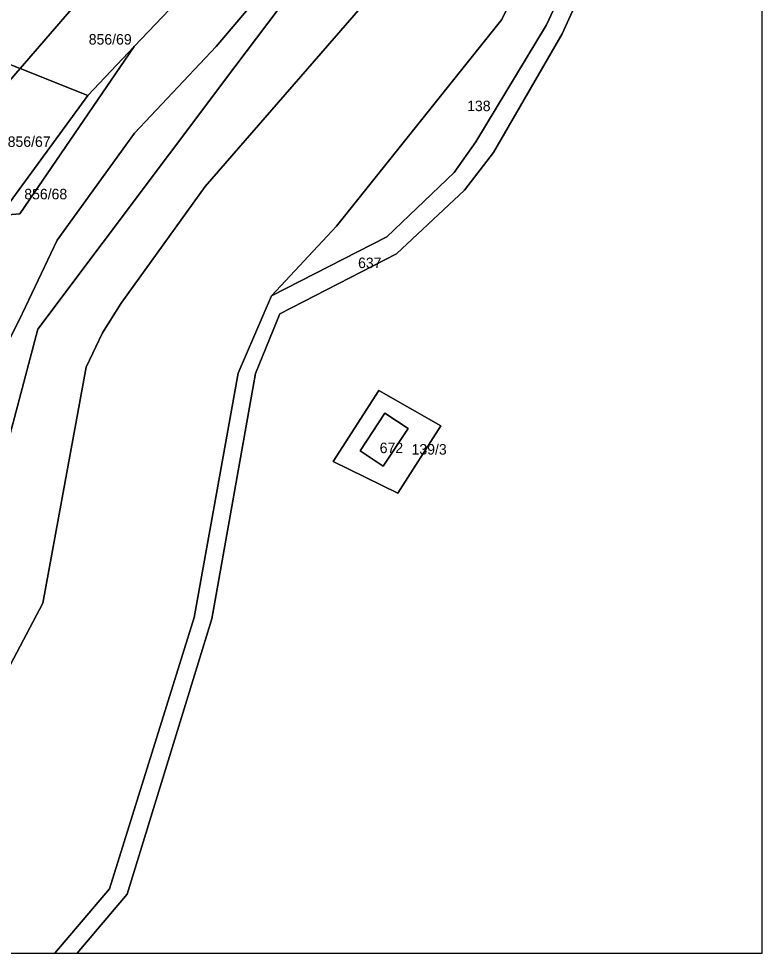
# Model space of a CAD drawing. Extents: x -564940 to -564406, y -1066466 to -1066072.
# Drawn here: x -564548.1 to -564406.4, y -1066465.6 to -1066287.6 of the extents above; entities that cross this region are included whole.
import ezdxf

# ---------------------------------------------------------------- set-up
doc = ezdxf.new("R2010")
doc.units = 0
doc.layers.add('ft_parcela_polygon', color=7, linetype='Continuous')
doc.layers.add('ft_parcela_text', color=7, linetype='Continuous')

msp = doc.modelspace()

# ---------------------------------------------------------------- linework, layer by layer
at = {"layer": 'ft_parcela_polygon'}
for p, q in [((-564582.26, -1066465.63), (-564541.21, -1066465.63)), ((-564541.21, -1066465.63), (-564536.97, -1066465.63))]:
    msp.add_line(p, q, dxfattribs=at)
for points in [[(-564506.93, -1066072.02), (-564500.76, -1066095.62), (-564490.54, -1066131.29), (-564485.08, -1066150.07), (-564474.86, -1066195.24), (-564468.44, -1066228.77), (-564474.86, -1066248.97), (-564479.58, -1066256.49), (-564510.51, -1066292.89), (-564526.05, -1066309.43), (-564540.77, -1066329.78), (-564548.05, -1066345), (-564588.23, -1066424.58), (-564607.75, -1066462.97), (-564609.27, -1066465.63)], [(-564609.27, -1066465.63), (-564607.75, -1066462.97), (-564588.23, -1066424.58), (-564548.05, -1066345), (-564540.77, -1066329.78), (-564526.05, -1066309.43), (-564510.51, -1066292.89), (-564479.58, -1066256.49), (-564474.86, -1066248.97), (-564468.44, -1066228.77), (-564474.86, -1066195.24), (-564485.08, -1066150.07), (-564490.54, -1066131.29), (-564500.76, -1066095.62), (-564506.93, -1066072.02)], [(-564600.77, -1066465.63), (-564576.34, -1066428.17), (-564561.1, -1066399.98), (-564552.57, -1066377.06), (-564544.46, -1066346.76), (-564506.9, -1066296.8), (-564477.41, -1066257.73), (-564467.26, -1066239.44), (-564459.83, -1066220.33), (-564457.63, -1066204.67), (-564458.61, -1066193.4), (-564464.89, -1066162.6), (-564473.06, -1066136.49), (-564496.21, -1066076.34), (-564497.57, -1066072.02)], [(-564497.57, -1066072.02), (-564496.21, -1066076.34), (-564473.06, -1066136.49), (-564464.89, -1066162.6), (-564458.61, -1066193.4), (-564457.63, -1066204.67), (-564459.83, -1066220.33), (-564467.26, -1066239.44), (-564477.41, -1066257.73), (-564506.9, -1066296.8), (-564544.46, -1066346.76), (-564552.57, -1066377.06), (-564561.1, -1066399.98), (-564576.34, -1066428.17), (-564600.77, -1066465.63)], [(-564428.01, -1066072.02), (-564431.34, -1066090.43), (-564438.01, -1066109.82), (-564446.27, -1066122.38), (-564434.59, -1066131.44), (-564440.14, -1066155.47), (-564448.27, -1066160.12), (-564443.92, -1066174.88), (-564442.56, -1066204.14), (-564447.75, -1066227.88), (-564462.14, -1066258.44), (-564480.38, -1066282.47), (-564512.56, -1066319.56), (-564528.58, -1066341.81), (-564532.13, -1066347.45), (-564535.25, -1066353.98), (-564543.55, -1066398.93), (-564558.38, -1066426.97), (-564582.26, -1066465.63)], [(-564582.26, -1066465.63), (-564558.38, -1066426.97), (-564543.55, -1066398.93), (-564535.25, -1066353.98), (-564532.13, -1066347.45), (-564528.58, -1066341.81), (-564512.56, -1066319.56), (-564480.38, -1066282.47), (-564462.14, -1066258.44), (-564447.75, -1066227.88), (-564442.56, -1066204.14), (-564443.92, -1066174.88), (-564448.27, -1066160.12), (-564456.43, -1066140.31), (-564460.8, -1066129.7), (-564472.45, -1066131.84), (-564488.63, -1066076.11), (-564489.48, -1066072.02)], [(-564541.21, -1066465.63), (-564530.8, -1066453.36), (-564514.67, -1066401.65), (-564506.28, -1066355.11), (-564499.92, -1066340.4), (-564487.53, -1066327.09), (-564456.06, -1066287.78), (-564438.54, -1066251.61), (-564424.63, -1066211.38), (-564406.38, -1066194.67)], [(-564406.38, -1066194.67), (-564424.63, -1066211.38), (-564434.8, -1066257.18), (-564442.13, -1066277.1), (-564447.53, -1066288.75), (-564461, -1066311.08), (-564465.11, -1066316.9), (-564477.95, -1066329.15), (-564499.92, -1066340.4), (-564506.28, -1066355.11), (-564514.67, -1066401.65), (-564530.8, -1066453.36), (-564541.21, -1066465.63)], [(-564536.97, -1066465.63), (-564406.38, -1066465.63), (-564406.38, -1066200.52)], [(-564406.38, -1066200.52), (-564421.59, -1066214.8), (-564431.36, -1066257.94), (-564438.67, -1066277.58), (-564444.56, -1066290.5), (-564457.61, -1066313.12), (-564463.15, -1066320.26), (-564476.08, -1066332.39), (-564498.32, -1066343.85), (-564502.98, -1066355.17), (-564511.33, -1066401.93), (-564527.46, -1066454.39), (-564536.97, -1066465.63)], [(-564536.97, -1066465.63), (-564527.46, -1066454.39), (-564511.33, -1066401.93), (-564502.98, -1066355.17), (-564498.32, -1066343.85), (-564476.08, -1066332.39), (-564463.15, -1066320.26), (-564457.61, -1066313.12), (-564444.56, -1066290.5), (-564438.67, -1066277.58), (-564431.36, -1066257.94), (-564421.59, -1066214.8), (-564406.38, -1066200.52)], [(-564519.39, -1066285.88), (-564526.09, -1066292.91), (-564547.92, -1066324.79), (-564551.67, -1066325.09), (-564555.65, -1066325.14), (-564559.33, -1066331.43), (-564556.55, -1066333.83), (-564553.56, -1066336.41), (-564579.89, -1066388.86), (-564586.69, -1066402.39), (-564589.7, -1066408.39), (-564595.81, -1066420.56), (-564609.5, -1066447.82), (-564620.81, -1066465.63)], [(-564467.66, -1066365.16), (-564475.84, -1066377.97), (-564488.17, -1066371.94), (-564479.46, -1066358.44), (-564467.66, -1066365.16)]]:
    msp.add_lwpolyline(points, dxfattribs=at)
for points in [[(-564499.92, -1066340.4), (-564477.95, -1066329.15), (-564465.11, -1066316.9), (-564461, -1066311.08), (-564447.53, -1066288.75), (-564442.13, -1066277.1), (-564434.8, -1066257.18), (-564424.63, -1066211.38), (-564438.54, -1066251.61), (-564456.06, -1066287.78), (-564487.53, -1066327.09)], [(-564532.7, -1066279.57), (-564567.5, -1066263.08), (-564578.22, -1066284.98), (-564558.28, -1066292.94), (-564547.86, -1066297.09)], [(-564534.97, -1066302.23), (-564526.09, -1066292.91), (-564519.39, -1066285.88), (-564532.7, -1066279.57), (-564547.86, -1066297.09)], [(-564547.86, -1066297.09), (-564558.28, -1066292.94), (-564559.2, -1066294.72), (-564561.47, -1066299.1), (-564565.88, -1066307.63), (-564568.76, -1066306.14), (-564574, -1066317.25), (-564567.34, -1066319.59)], [(-564551.67, -1066325.09), (-564547.92, -1066324.79), (-564526.09, -1066292.91), (-564534.97, -1066302.23)], [(-564567.34, -1066319.59), (-564551.67, -1066325.09), (-564534.97, -1066302.23), (-564547.86, -1066297.09)], [(-564488.17, -1066371.94), (-564475.84, -1066377.97), (-564467.66, -1066365.16), (-564479.46, -1066358.44)], [(-564473.88, -1066365.68), (-564478.3, -1066362.75), (-564483.04, -1066369.89), (-564478.62, -1066372.82)], [(-564483.04, -1066369.89), (-564478.3, -1066362.75), (-564473.88, -1066365.68), (-564478.62, -1066372.82)]]:
    msp.add_lwpolyline(points, close=True, dxfattribs=at)

# ---------------------------------------------------------------- texts
at = {"layer": 'ft_parcela_text'}
for s, p in [('856/69', (-564534.77, -1066292.53)), ('138', (-564462.64, -1066305.21)), ('856/67', (-564550.22, -1066312.02)), ('856/68', (-564547.06, -1066322.01)), ('637', (-564483.43, -1066335.11)), ('672', (-564479.31, -1066370.36)), ('139/3', (-564473.23, -1066370.63))]:
    msp.add_text(s, height=2, dxfattribs=at).set_placement(p)

doc.saveas('drawing.dxf')
